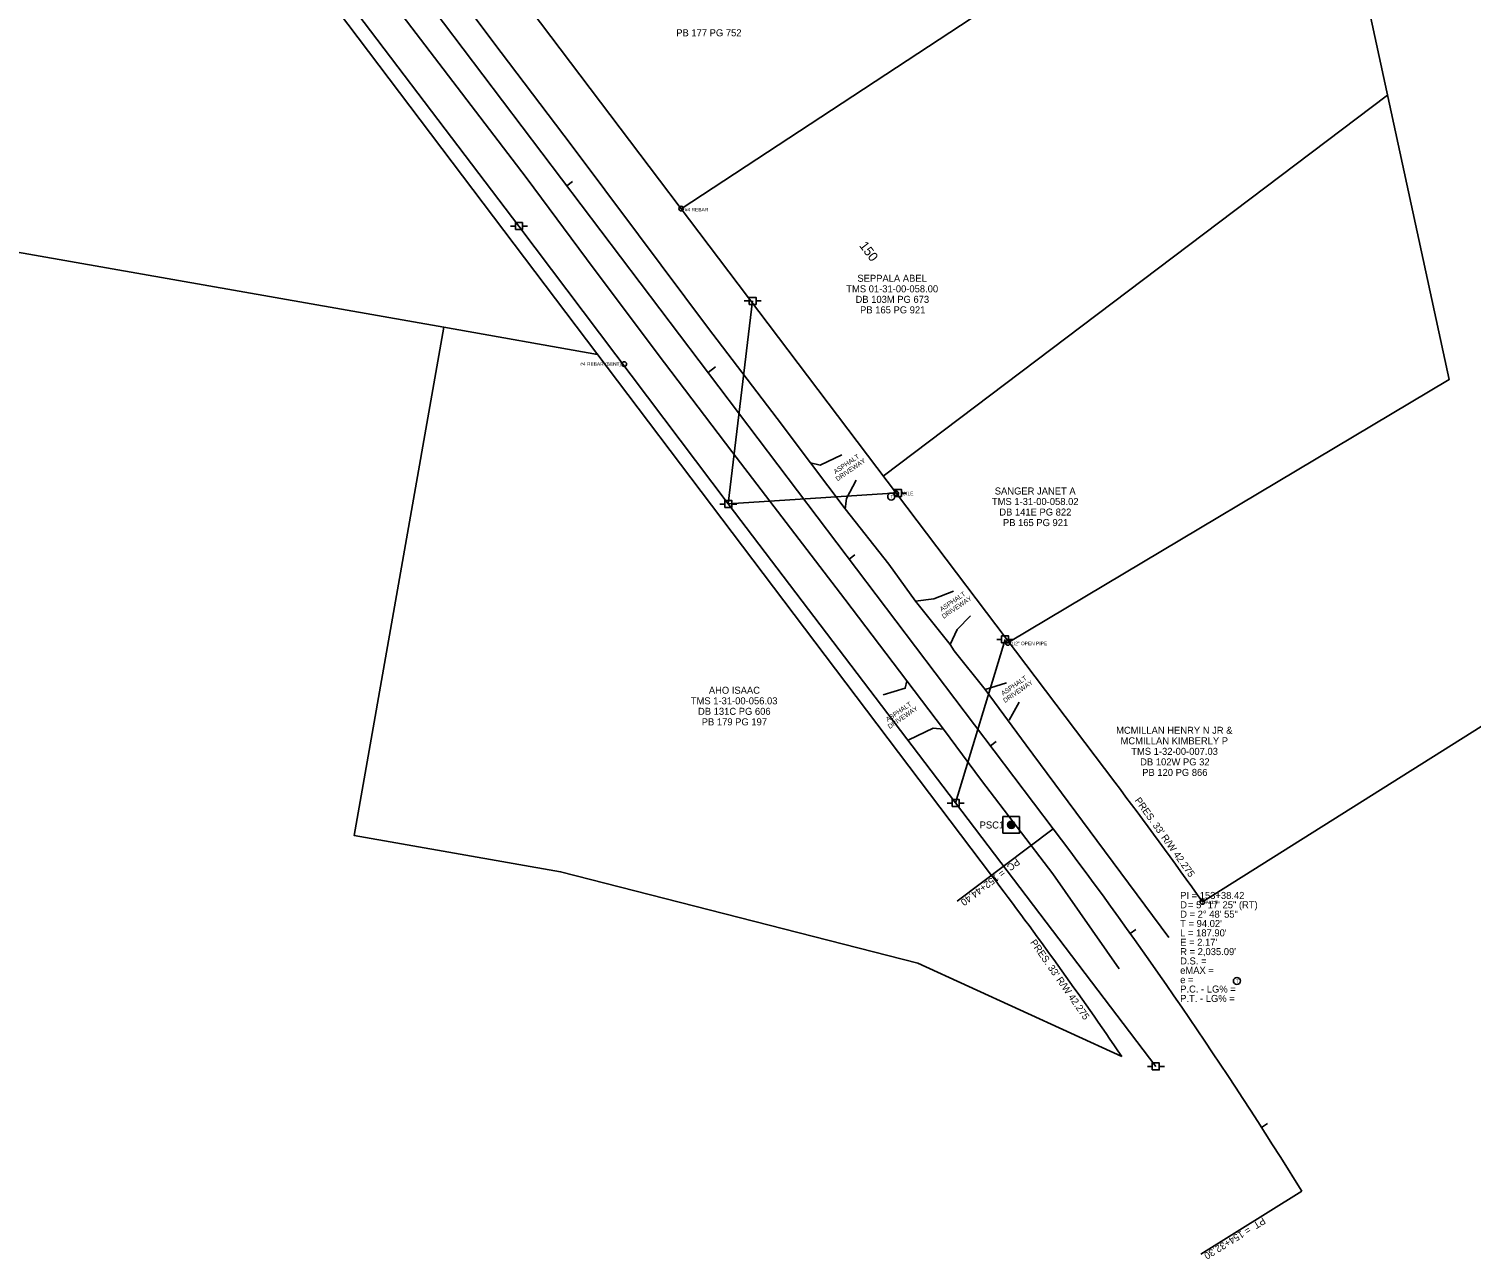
# Model space of a CAD drawing. Extents: x 1642870 to 1644553, y 1183846 to 1185844.
# Drawn here: x 1643608 to 1644224, y 1184202 to 1184728 of the extents above; entities that cross this region are included whole.
import ezdxf

# ---------------------------------------------------------------- set-up
doc = ezdxf.new("R2010")
doc.units = 0
for name, color, linetype in [('RD_EX_DV_Prop', 7, 'Continuous'), ('RD_EX_DV_Prop_txCode', 7, 'Continuous'), ('RD_EX_DV_PropPin', 7, 'Continuous'), ('RD_EX_DV_TX_Prop', 7, 'Continuous'), ('RD_EX_Road', 7, 'Continuous'), ('RD_EX_RW', 7, 'Continuous'), ('RD_EX_RW_TX', 7, 'Continuous'), ('RD_EX_UT', 7, 'Continuous'), ('RD_HC_Cl', 7, 'Continuous'), ('RD_HC_Data', 7, 'Continuous'), ('RD_HC_Data_Tic', 7, 'Continuous'), ('RD_HC_Survey', 7, 'Continuous'), ('RD_HC_Survey_txCode', 7, 'Continuous'), ('RD_HC_TX_Sta20', 7, 'Continuous'), ('RD_TX_Misc1', 7, 'Continuous')]:
    doc.layers.add(name, color=color, linetype=linetype)

msp = doc.modelspace()

# ---------------------------------------------------------------- linework, layer by layer
at = {"layer": 'RD_EX_DV_Prop'}
for p, q in [((1644188.56, 1184699.36), (1643973.18, 1184536.66)), ((1643851.12, 1184588.64), (1643785.36, 1184600.22))]:
    msp.add_line(p, q, dxfattribs=at)
for points in [[(1644383.88, 1184957.62), (1644160.78, 1184830.87), (1644098.09, 1184789.7), (1643886.79, 1184650.9)], [(1644383.88, 1184957.62), (1644552.72, 1184633.56), (1644109.52, 1184354.74)], [(1644026.86, 1184465.66), (1644214.86, 1184577.89), (1644160.18, 1184830.48)], [(1644075.07, 1184288.72), (1643987.91, 1184328.61), (1643835.33, 1184367.62), (1643747.11, 1184383.16), (1643785.36, 1184600.22), (1643553.7, 1184641.03)]]:
    msp.add_lwpolyline(points, dxfattribs=at)
at = {"layer": 'RD_EX_DV_PropPin'}
for centre in [(1643886.81, 1184650.92), (1643862.48, 1184584.52), (1643978.71, 1184529.26), (1644026.39, 1184465.38), (1644109.48, 1184354.72)]:
    msp.add_circle(centre, 1, dxfattribs=at)
at = {"layer": 'RD_EX_Road'}
for points in [[(1644073.99, 1184326.12), (1644045.6, 1184366.75), (1644015.16, 1184406.64), (1643998.93, 1184428.49), (1643983.25, 1184449.14), (1643956.67, 1184484.03), (1643908.42, 1184547.11), (1643879.67, 1184585.06), (1643849.7, 1184625.13), (1643820.64, 1184664.16), (1643791.09, 1184702.78), (1643757.99, 1184746.42), (1643727.17, 1184787.53), (1643696.82, 1184827.61), (1643674.57, 1184857.51), (1643649.6, 1184890.04), (1643644.71, 1184897.22), (1643610.96, 1184937.11)], [(1644095.12, 1184339.48), (1644064.35, 1184381.04), (1644034.15, 1184421.72), (1644016.63, 1184445.53), (1644003.48, 1184462.02), (1644001.77, 1184464.74), (1643986.92, 1184483.24), (1643975.48, 1184499.01), (1643956.83, 1184522.62), (1643942.03, 1184542.37), (1643927.77, 1184561.3), (1643898.11, 1184600.21), (1643868.64, 1184639.74), (1643839.83, 1184678.25), (1643809.94, 1184717.64), (1643791.44, 1184742.35)], [(1643955.49, 1184545.68), (1643946.17, 1184541.37), (1643942.03, 1184542.37)], [(1643956.83, 1184522.62), (1643957.41, 1184527.14), (1643961.52, 1184534.93)], [(1644003.14, 1184487.51), (1643994.81, 1184484.27), (1643986.92, 1184483.24)], [(1644001.77, 1184464.74), (1644004.68, 1184471.17), (1644010.45, 1184477.01)], [(1643973.04, 1184443.2), (1643982.56, 1184446.03), (1643983.25, 1184449.14)], [(1644025.76, 1184448.36), (1644016.63, 1184445.53)], [(1644026.9, 1184432.42), (1644031.25, 1184440.02)], [(1643998.93, 1184428.49), (1643994.48, 1184428.9), (1643984.13, 1184423.96)]]:
    msp.add_lwpolyline(points, dxfattribs=at)
at = {"layer": 'RD_EX_RW'}
for p, q in [((1643225.58, 1185525.31), (1644072.06, 1184405.88)), ((1643193.75, 1185457.98), (1644019.42, 1184366.08))]:
    msp.add_line(p, q, dxfattribs=at)
for radius, start in [(2068.09, 35.33934), (2002.09, 34.36834)]:
    msp.add_arc((1642422.49, 1183158.52), radius, start, 37.09555, dxfattribs=at)
at = {"layer": 'RD_EX_UT'}
for p, q in [((1643813.95, 1184643.46), (1643816.01, 1184643.46)), ((1643817.51, 1184643.49), (1643817.51, 1184643.49)), ((1643819.01, 1184643.46), (1643821.15, 1184643.46)), ((1643913.77, 1184611.47), (1643915.82, 1184611.47)), ((1643917.32, 1184611.5), (1643917.32, 1184611.5)), ((1643918.82, 1184611.47), (1643920.96, 1184611.47)), ((1643906.91, 1184524.77), (1643979.44, 1184529.46)), ((1643975.88, 1184529.42), (1643977.94, 1184529.42)), ((1643979.44, 1184529.46), (1643979.44, 1184529.46)), ((1643980.94, 1184529.42), (1643983.08, 1184529.42)), ((1643903.35, 1184524.73), (1643905.4, 1184524.73)), ((1643906.91, 1184524.77), (1643906.91, 1184524.77)), ((1643908.4, 1184524.73), (1643910.55, 1184524.73)), ((1644004.02, 1184397), (1644025.18, 1184466.9)), ((1644021.62, 1184466.87), (1644023.68, 1184466.87)), ((1644025.18, 1184466.9), (1644025.18, 1184466.9)), ((1644026.68, 1184466.87), (1644028.82, 1184466.87)), ((1644000.46, 1184396.96), (1644002.52, 1184396.96)), ((1644004.02, 1184397), (1644004.02, 1184397)), ((1644005.52, 1184396.96), (1644007.66, 1184396.96)), ((1644086.03, 1184284.41), (1644088.09, 1184284.42)), ((1644089.59, 1184284.45), (1644089.59, 1184284.45)), ((1644091.09, 1184284.42), (1644093.23, 1184284.41))]:
    msp.add_line(p, q, dxfattribs=at)
for points in [[(1643725.28, 1184764.93), (1643817.51, 1184643.49), (1643906.91, 1184524.77), (1643917.32, 1184611.5)], [(1643906.91, 1184524.77), (1644004.02, 1184397), (1644089.59, 1184284.45)]]:
    msp.add_lwpolyline(points, dxfattribs=at)
for points in [[(1643816.01, 1184641.99), (1643816.01, 1184644.99), (1643819.01, 1184644.99), (1643819.01, 1184641.99)], [(1643915.82, 1184610), (1643915.82, 1184613), (1643918.82, 1184613), (1643918.82, 1184610)], [(1643977.94, 1184527.96), (1643977.94, 1184530.96), (1643980.94, 1184530.96), (1643980.94, 1184527.96)], [(1643905.4, 1184523.27), (1643905.41, 1184526.27), (1643908.4, 1184526.27), (1643908.4, 1184523.27)], [(1644023.68, 1184465.4), (1644023.68, 1184468.4), (1644026.68, 1184468.4), (1644026.68, 1184465.4)], [(1644002.52, 1184395.5), (1644002.52, 1184398.5), (1644005.52, 1184398.5), (1644005.52, 1184395.5)], [(1644088.09, 1184282.95), (1644088.09, 1184285.95), (1644091.09, 1184285.95), (1644091.09, 1184282.95)]]:
    msp.add_lwpolyline(points, close=True, dxfattribs=at)
for centre in [(1643976.55, 1184527.92), (1644124.21, 1184320.98)]:
    msp.add_circle(centre, 1.5, dxfattribs=at)
at = {"layer": 'RD_HC_Cl'}
msp.add_line((1643229.22, 1185465.79), (1644045.74, 1184385.98), dxfattribs=at)
msp.add_arc((1642422.49, 1183158.52), 2035.09, 31.80537, 37.09555, dxfattribs=at)
at = {"layer": 'RD_HC_Data'}
for p, q in [((1644045.74, 1184385.98), (1644004.78, 1184355)), ((1644152, 1184231.09), (1644108.77, 1184204.28))]:
    msp.add_line(p, q, dxfattribs=at)
at = {"layer": 'RD_HC_Data_Tic'}
for p, q in [((1643838.02, 1184660.68), (1643840.41, 1184662.49)), ((1643898.33, 1184580.92), (1643901.52, 1184583.33)), ((1643958.65, 1184501.16), (1643961.04, 1184502.97)), ((1644018.96, 1184421.4), (1644021.35, 1184423.2)), ((1644078.67, 1184341.18), (1644081.11, 1184342.92)), ((1644134.76, 1184258.4), (1644137.28, 1184260.03))]:
    msp.add_line(p, q, dxfattribs=at)
at = {"layer": 'RD_HC_Survey'}
for p, q in [((1644026.32, 1184387.33), (1644026.32, 1184388.05)), ((1644026.37, 1184387.16), (1644026.37, 1184388.22)), ((1644026.42, 1184387.04), (1644026.42, 1184388.34)), ((1644026.47, 1184386.94), (1644026.47, 1184388.44)), ((1644026.52, 1184386.85), (1644026.52, 1184388.52)), ((1644026.57, 1184386.78), (1644026.57, 1184388.59)), ((1644026.62, 1184386.71), (1644026.62, 1184388.66)), ((1644026.67, 1184386.65), (1644026.67, 1184388.72)), ((1644026.72, 1184386.6), (1644026.72, 1184388.77)), ((1644026.77, 1184386.55), (1644026.77, 1184388.82)), ((1644026.82, 1184386.51), (1644026.82, 1184388.87)), ((1644026.87, 1184386.47), (1644026.87, 1184388.91)), ((1644026.92, 1184386.43), (1644026.92, 1184388.95)), ((1644026.97, 1184386.39), (1644026.97, 1184388.98)), ((1644027.02, 1184386.36), (1644027.02, 1184389.01)), ((1644027.07, 1184386.33), (1644027.07, 1184389.04)), ((1644027.12, 1184386.3), (1644027.12, 1184389.07)), ((1644027.17, 1184386.28), (1644027.17, 1184389.09)), ((1644027.22, 1184386.26), (1644027.22, 1184389.12)), ((1644027.27, 1184386.24), (1644027.27, 1184389.14)), ((1644027.32, 1184386.22), (1644027.32, 1184389.15)), ((1644027.37, 1184386.2), (1644027.37, 1184389.17)), ((1644027.42, 1184386.19), (1644027.42, 1184389.19)), ((1644027.47, 1184386.18), (1644027.47, 1184389.2)), ((1644027.52, 1184386.16), (1644027.52, 1184389.21)), ((1644027.57, 1184386.15), (1644027.57, 1184389.22)), ((1644027.62, 1184386.15), (1644027.62, 1184389.23)), ((1644027.67, 1184386.14), (1644027.67, 1184389.23)), ((1644027.72, 1184386.14), (1644027.72, 1184389.24)), ((1644027.77, 1184386.13), (1644027.77, 1184389.24)), ((1644027.82, 1184386.13), (1644027.82, 1184389.24)), ((1644027.87, 1184386.13), (1644027.87, 1184389.24)), ((1644027.92, 1184386.13), (1644027.92, 1184389.24)), ((1644027.97, 1184386.14), (1644027.97, 1184389.24)), ((1644028.02, 1184386.14), (1644028.02, 1184389.23)), ((1644028.07, 1184386.15), (1644028.07, 1184389.22)), ((1644028.12, 1184386.16), (1644028.12, 1184389.21)), ((1644028.17, 1184386.17), (1644028.17, 1184389.2)), ((1644028.22, 1184386.18), (1644028.22, 1184389.19)), ((1644028.27, 1184386.2), (1644028.27, 1184389.18)), ((1644028.32, 1184386.21), (1644028.32, 1184389.16)), ((1644028.37, 1184386.23), (1644028.37, 1184389.15)), ((1644028.42, 1184386.25), (1644028.42, 1184389.13)), ((1644028.47, 1184386.27), (1644028.47, 1184389.1)), ((1644028.52, 1184386.29), (1644028.52, 1184389.08)), ((1644028.57, 1184386.32), (1644028.57, 1184389.06)), ((1644028.62, 1184386.35), (1644028.62, 1184389.03)), ((1644028.67, 1184386.38), (1644028.67, 1184389)), ((1644028.72, 1184386.41), (1644028.72, 1184388.96)), ((1644028.77, 1184386.45), (1644028.77, 1184388.93)), ((1644028.82, 1184386.49), (1644028.82, 1184388.89)), ((1644028.87, 1184386.53), (1644028.87, 1184388.84)), ((1644028.92, 1184386.58), (1644028.92, 1184388.8)), ((1644028.97, 1184386.63), (1644028.97, 1184388.75)), ((1644029.02, 1184386.68), (1644029.02, 1184388.69)), ((1644029.07, 1184386.75), (1644029.07, 1184388.63)), ((1644029.12, 1184386.82), (1644029.12, 1184388.56)), ((1644029.17, 1184386.9), (1644029.17, 1184388.48)), ((1644029.22, 1184386.99), (1644029.22, 1184388.39)), ((1644029.27, 1184387.1), (1644029.27, 1184388.28)), ((1644029.32, 1184387.24), (1644029.32, 1184388.14)), ((1644029.37, 1184387.46), (1644029.37, 1184387.91))]:
    msp.add_line(p, q, dxfattribs=at)
msp.add_lwpolyline([(1644031.37, 1184391.22), (1644024.3, 1184391.22), (1644024.3, 1184384.15), (1644031.37, 1184384.15)], close=True, dxfattribs=at)
msp.add_circle((1644027.84, 1184387.69), 1.55, dxfattribs=at)

# ---------------------------------------------------------------- texts
at = {"layer": 'RD_EX_DV_Prop_txCode'}
for s, p in [('#4 REBAR', (1643888.39, 1184649.74)), ('#4 REBAR (BENT)', (1643843.68, 1184583.78)), ('AXLE', (1643980.72, 1184528.48)), ('1/2" OPEN PIPE', (1644027.8, 1184464.4)), ('AXLE', (1644110.86, 1184353.79))]:
    msp.add_text(s, height=1.5, dxfattribs=at).set_placement(p)
at = {"layer": 'RD_EX_DV_TX_Prop'}
for s, p in [('PB 177 PG 752', (1643884.72, 1184724.55)), ('SEPPALA ABEL', (1643962.1, 1184619.67)), ('TMS 01-31-00-058.00', (1643957.35, 1184615.17)), ('DB 103M PG 673', (1643961.31, 1184610.67)), ('PB 165 PG 921', (1643963.26, 1184606.17)), ('TMS 1-31-00-058.02', (1644019.56, 1184524.29)), ('SANGER JANET A', (1644020.78, 1184528.79)), ('DB 141E PG 822', (1644022.73, 1184519.79)), ('PB 165 PG 921', (1644024.28, 1184515.29)), ('AHO ISAAC', (1643898.64, 1184443.66)), ('TMS 1-31-00-056.03', (1643890.94, 1184439.16)), ('DB 131C PG 606', (1643894.02, 1184434.66)), ('PB 179 PG 197', (1643895.61, 1184430.16)), ('MCMILLAN HENRY N JR &', (1644072.63, 1184426.56)), ('MCMILLAN KIMBERLY P', (1644074.52, 1184422.06)), ('TMS 1-32-00-007.03', (1644079.1, 1184417.56)), ('DB 102W PG 32', (1644082.9, 1184413.06)), ('PB 120 PG 866', (1644083.77, 1184408.56))]:
    msp.add_text(s, height=3, dxfattribs=at).set_placement(p)
at = {"layer": 'RD_EX_RW_TX'}
for rotation, p in [(305.52399, (1644080.42, 1184398.09)), (304.85132, (1644035.78, 1184337.4))]:
    msp.add_text("PRES. 33' R/W 42.275", height=3, rotation=rotation, dxfattribs=at).set_placement(p)
at = {"layer": 'RD_EX_UT'}
for p in [(1643976.2, 1184527.1), (1644123.86, 1184320.16)]:
    msp.add_text('T', height=1.5, rotation=360, dxfattribs=at).set_placement(p)
at = {"layer": 'RD_HC_Data'}
for s, rotation, p in [('PC  = 152+44.40', 217.09555, (1644030.09, 1184373.52)), ('PT  = 154+32.30', 211.80537, (1644135.27, 1184220.12))]:
    msp.add_text(s, height=3, rotation=rotation, dxfattribs=at).set_placement(p)
for s, p in [('PI = 153+38.42', (1644100, 1184356)), ('D', (1644100, 1184352)), ('   = 5%%d 17\' 25" (RT)', (1644100, 1184352)), ('D = 2%%d 48\' 55"', (1644100, 1184348)), ("T = 94.02'", (1644100, 1184344)), ("L = 187.90'", (1644100, 1184340)), ("E = 2.17'", (1644100, 1184336)), ("R = 2,035.09'", (1644100, 1184332)), ('D.S. = ', (1644100, 1184328)), ('eMAX = ', (1644100, 1184324)), ('e = ', (1644100, 1184320)), ('P.C. - LG% = ', (1644100, 1184316)), ('P.T. - LG% = ', (1644100, 1184312))]:
    msp.add_text(s, height=3, dxfattribs=at).set_placement(p)
at = {"layer": 'RD_HC_Survey_txCode'}
msp.add_text('PSC1', height=3, dxfattribs=at).set_placement((1644014.33, 1184386.1))
at = {"layer": 'RD_HC_TX_Sta20'}
msp.add_text('150', height=4, rotation=307.09555, dxfattribs=at).set_placement((1643962.7, 1184635.07))
at = {"layer": 'RD_TX_Misc1'}
for s, p in [('ASPHALT', (1643952.78, 1184537.45)), ('DRIVEWAY', (1643953.64, 1184534.4)), ('ASPHALT', (1643998.14, 1184478.69)), ('DRIVEWAY', (1643999, 1184475.64)), ('ASPHALT', (1644024.33, 1184442.75)), ('DRIVEWAY', (1644025.19, 1184439.7)), ('ASPHALT', (1643975.08, 1184431.62)), ('DRIVEWAY', (1643975.94, 1184428.58))]:
    msp.add_text(s, height=2, rotation=34.52966, dxfattribs=at).set_placement(p)

doc.saveas('drawing.dxf')
